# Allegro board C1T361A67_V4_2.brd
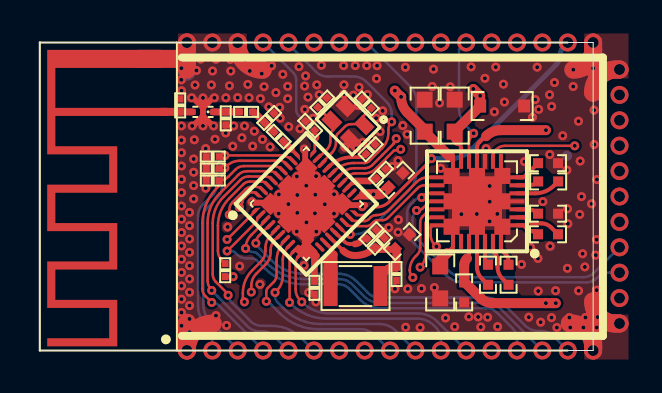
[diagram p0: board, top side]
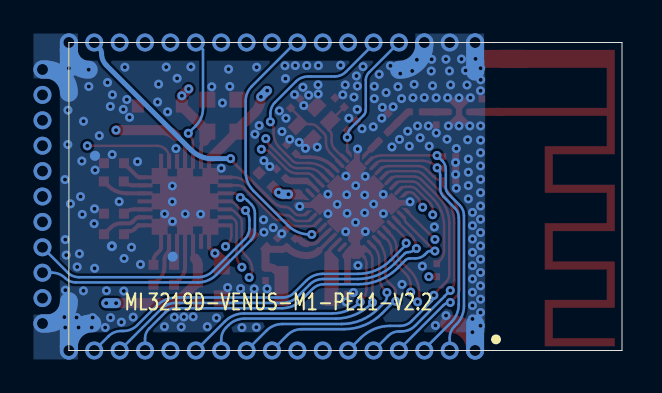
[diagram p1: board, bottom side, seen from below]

Outline 27.67 x 15.4 mm; copper layers: TOP, GND, POWER, BOTTOM. Coordinates in mm from the lower left corner of the outline.
Outline path: 0,15.4 27.67,15.4 27.67,0 26.4,0 0,0 0,15.4

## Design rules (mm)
constraint set DEFAULT: min track width 0.127, pair gap 0.1

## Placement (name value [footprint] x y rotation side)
C1  220pF  [0201]  11.94 10.69 135 top
C2  NC  [0201]  11.46 11.63 45 top
C3  NC  [0201]  9.29 11.61 270 top
C5  1uF  [0201]  13.51 11.24 315 top
C6  1uF  [0201]  16.54 10.06 45 top
C7  10uF  [0402]  17.8 8.52 45 top
C8  1uF  [0201]  17.06 8.84 45 top
C10  NC  [0201]  14.12 12.4 45 top
C11  NC  [0201]  16.35 12.35 315 top
C12  2.2uF  [0201]  13.73 3.14 90 top
C13  1uF  [0201]  16.58 5.82 45 top
C14  NC/2.2uF  [0201]  17.83 3.82 270 top
C15  1uF  [0402]  23.44 3.79 90 top
C16  1uF  [0402]  22.41 3.79 90 top
C17  47uF  [0603C]  20.02 3.4 270 top
C18  470nF  [0402]  25.41 5.81 180 top
C19  100nF  [0402]  25.41 6.84 180 top
C20  100nF  [0402]  21.22 2.91 90 top
C21  NC/3.9pF  [0201]  8.64 8.5 0 top
C22  NC/3.9pF  [0201]  8.64 9.1 0 top
C23  NC/3.9pF  [0201]  8.64 9.7 180 top
C24  10uF  [0402]  18.12 5.44 45 top
C25  0.1uF  [0201]  17 5.39 45 top
C26  100nF  [0402]  25.42 8.45 180 top
C27  100nF  [0402]  25.41 9.37 180 top
C28  47uF  [0603C]  19.24 11.74 90 top
C29  47uF  [0603C]  20.74 11.74 90 top
C30  LFB152G45CB2D320  [0402_D]  8.15 11.93 0 top
D1  ULC0322P10LV  [0201]  7.01 12.25 270 top
D2  PESD3V3L1BAF  [SOD323]  23.12 12.22 180 top
L1  0R  [0201]  10.31 11.93 180 top
L3  6.8uH  [1008L]  15.78 3.22 180 top
R1  510R  [0201]  9.27 4.02 90 top
U1  TL3219D  [QFN_4X4_38PIN_0P35_2P9X2P9]  13.32 7.33 45 top
U2  NEH7100  [QFN_4X4_28PIN_0P4_2P5X2P5]  21.86 7.46 180 top
U3  MODULE_15p4mm  [MODULE_BUTEO_EH_1211]  15.61 8.97 0 top
Y1  24MHz-12pF-+/-10ppm  [OSCCC160X200X065]  15.45 11.41 135 top

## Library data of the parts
C1-C3 C10 C11 = C1608_NC: User Part Number: pn; Tolerance: RichardLC
C5 C6 C8 C12-C14 C21-C23 C25 = C1005X5R1C104K: User Part Number: pn; Tolerance: RichardLC
C7 C15-C20 C24 C26-C29 = C1005X5R1C104K
C30 = C1608_NC_4
D1 = DIODE SCHOTTKY_0: User Part Number: pn; Tolerance: RichardLC
D2 = DIODE SCHOTTKY_0
L1 = MLK1608_000R: User Part Number: pn; Tolerance: RichardLC
L3 = IND_0: User Part Number: pn; Tolerance: RichardLC
R1 = RS0603K330JT: User Part Number: pn; Tolerance: RichardLC
U1 = TL3219D: Tolerance: RichardLC
U2 = TLSR9517C_9: Tolerance: RichardLC
U3 = TLSR8868ET48_14: User Part Number: PN
Y1 = CRYSTAL4/SM_0

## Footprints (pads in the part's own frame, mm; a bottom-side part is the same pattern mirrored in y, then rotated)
0201
  rect 0.35x0.33 smd: 1(-0.325,0) 2(0.325,0)
0402
  rect 0.5x0.5 smd: 1(-0.5,0) 2(0.5,0)
0402_D
  rect 0.3x0.3 smd: 1(0,0.3) 3(0,-0.3)
  rect 0.35x0.3 smd: 2(0.54,0) 4(-0.54,0)
0603C
  rect 0.8x0.8 smd: 1(-0.8,0) 2(0.8,0)
1008L
  rect 0.7x2 smd: 1(-1.25,0) 2(1.25,0)
MODULE_BUTEO_EH_1211
  rect 0.25x0.25 smd: 1(-8.255,-8.97) 2(-6.985,-8.97) 3(-5.715,-8.97) 4(-4.445,-8.97) 5(-3.175,-8.97) 6(-1.905,-8.97) 7(-0.635,-8.97) 8(0.635,-8.97) 9(1.905,-8.97) 10(3.175,-8.97) 11(4.445,-8.97) 12(5.715,-8.97) 13(6.985,-8.97) 14(8.255,-8.97) 15(9.525,-8.97) 16(10.795,-8.97) 17(12.065,-8.97) 18(13.385,-7.62) 19(13.385,-6.35) 20(13.385,-5.08) 21(13.385,-3.81) 22(13.385,-2.54) 23(13.385,-1.27) 24(13.385,0) 25(13.385,1.27) 26(13.385,2.54) 27(13.385,3.81) 28(13.385,5.08) 29(12.065,6.43) 30(10.795,6.43) 31(9.525,6.43) 32(8.255,6.43) 33(6.985,6.43) 34(5.715,6.43) 35(4.445,6.43) 36(3.175,6.43) 37(1.905,6.43) 38(0.635,6.43) 39(-0.635,6.43) 40(-1.905,6.43) 41(-3.175,6.43) 42(-4.445,6.43) 43(-5.715,6.43) 44(-6.985,6.43) 45(-8.255,6.43)
  rect 0.8x0.8 smd rot 45: 46(-2.281,0.155) 47(-3.179,-0.744) 48(-4.077,-1.641) 49(-1.383,-0.744) 50(-2.281,-1.641) 51(-3.179,-2.539) 52(-0.485,-1.641) 53(-1.383,-2.539)
  custom 0.2x0.2 smd rot 45: 54(-2.281,-4.003)
  rect 0.8x0.8 smd: 55(4.985,-0.241) 56(6.255,-0.241) 57(7.525,-0.241) 58(4.985,-1.512) 59(6.255,-1.512) 60(7.525,-1.512) 61(4.985,-2.781) 62(6.255,-2.781) 63(7.525,-2.781)
OSCCC160X200X065
  rect 0.85x0.6 smd: 1(-0.65,-0.45) 4(-0.65,0.55)
  rect 0.85x0.65 smd: 2(0.65,-0.45) 3(0.65,0.55)
QFN_4X4_28PIN_0P4_2P5X2P5
  rect 0.75x0.2 smd: 1(-2,1.2) 2(-2,0.8) 3(-2,0.4) 4(-2,0) 5(-2,-0.4) 6(-2,-0.8) 7(-2,-1.2) 15(2,-1.2) 16(2,-0.8) 17(2,-0.4) 18(2,0) 19(2,0.4) 20(2,0.8) 21(2,1.2)
  rect 0.2x0.75 smd: 8(-1.2,-2) 9(-0.8,-2) 10(-0.4,-2) 11(0,-2) 12(0.4,-2) 13(0.8,-2) 14(1.2,-2) 22(1.2,2) 23(0.8,2) 24(0.4,2) 25(0,2) 26(-0.4,2) 27(-0.8,2) 28(-1.2,2)
  rect 2.5x2.5 smd: 29(0,0)
QFN_4X4_38PIN_0P35_2P9X2P9
  custom 0.045x0.045 smd: 1(-2,1.575) 10(-2,-1.575) 11(-1.4,-2) 19(1.4,-2) 20(2,-1.575) 29(2,1.575) 30(1.4,2) 38(-1.4,2)
  oval 0.6x0.18 smd: 2(-2,1.225) 3(-2,0.875) 4(-2,0.525) 5(-2,0.175) 6(-2,-0.175) 7(-2,-0.525) 8(-2,-0.875) 9(-2,-1.225) 21(2,-1.225) 22(2,-0.875) 23(2,-0.525) 24(2,-0.175) 25(2,0.175) 26(2,0.525) 27(2,0.875) 28(2,1.225)
  oval 0.18x0.6 smd: 12(-1.05,-2) 13(-0.7,-2) 14(-0.35,-2) 15(0,-2) 16(0.35,-2) 17(0.7,-2) 18(1.05,-2) 31(1.05,2) 32(0.7,2) 33(0.35,2) 34(0,2) 35(-0.35,2) 36(-0.7,2) 37(-1.05,2)
  custom 0.725x0.725 smd: 39(0,0)
SOD323
  rect 0.6x0.65 smd: 1(-1.1,0) 2(1.1,0)

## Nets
GND: C2.2 C3.2 C5.1 C6.2 C7.2 C8.2 C10.2 C11.1 C12.1 C13.2 C14.2 C17.2 C19.1 C20.1 C21.1 C22.1 C23.2 C24.2 C25.2 C27.1 C28.2 C29.2 C30.1 C30.3 C30.4 D1.1 D1.2(CATHODE) D2.1 U1.39 U2.4 U2.10 U2.29 U3.1 U3.17 U3.18 U3.28 U3.29 U3.43 U3.44 U3.45 U3.46 U3.47 U3.48 U3.49 U3.50 U3.51 U3.52 U3.53 U3.54 U3.55 U3.56 U3.57 U3.58 U3.59 U3.60 U3.61 U3.62 U3.63 Y1.2 Y1.4
NEH_CSTORE: C17.1 U2.22 U3.25
NEH_HC0: U2.21 U3.24
NEH_HC1: U2.20 U3.23
NEH_HC2: U2.19 U3.22
NEH_HC3: U2.18 U3.21
NEH_HC4: U2.17 U3.20
NEH_LDOEN: U2.12 U3.34
NEH_SCL: U1.17 U2.16
NEH_SDA: U1.18 U2.15
NEH_USB: U2.11 U3.27
NEH_VBAT: C28.1 U2.14 U3.37
NEH_VBATOK: U2.9 U3.26
NEH_VIN: C20.2 U2.24 U3.19
NEH_VLDO: C29.1 D2.2(CATHODE) U2.13(VLDO) U3.35
TL_ANT: C1.1 U1.30
TL_AVDD1P25: C14.1 C24.1 C25.1 L3.1 U1.14
TL_AVDD3: C8.1 U1.22
TL_IR: U1.19 U3.30
TL_PA0: U1.37 U3.32
TL_PA1: U1.7 U3.9(PIN9)
TL_PA2: U1.8 U3.10
TL_PA3: U1.10 U3.12
TL_PA4: U1.9 U3.11
TL_PA5_DM: U1.6 U3.8
TL_PA6_DP: U1.5 U3.7
TL_PA7_SWS: R1.1 U3.13
TL_PB0: U1.1 U3.31
TL_PB1: U1.38 U3.33
TL_PB7: U1.16 U3.38
TL_PC0_AMICP: U1.23 U3.40
TL_PC1_AMICN: U1.24 U3.39
TL_PC2: U1.25 U3.41
TL_PD1: U1.2 U3.14
TL_PD4: U1.3 U3.15
TL_PD6: U1.4 U3.16
TL_PE2: C21.2 U1.33 U3.4
TL_PE4: C23.1 U1.31 U3.2
TL_PE5: C22.2 U1.32 U3.3
TL_PE6: U1.35 U3.6
TL_PE7: U1.34 U3.5
TL_RESET: C5.2 U1.29 U3.42
TL_VBAT: C7.1 U1.20 U3.36
TL_XC1: C10.1 U1.28 Y1.3
TL_XC2: C11.2 U1.27(XC2) Y1.1
N20494255: C1.2 C2.1 L1.1
N20494385: C3.1 C30.2 L1.2
N20502827: C6.1 U1.26
N20503268: C12.2 U1.11
N20503276: C13.1 U1.15
N20503917: L3.2 U1.13
N20508843: C16.1 U2.25
N20508848: C16.2 U2.26
N20508856: C15.1 U2.27
N20508888: C15.2 U2.28
N20508941: C18.2 U2.1
N20508944: C18.1 U2.2
N20508953: C26.1 U2.5
N20508962: C26.2 U2.6
N20508983: C19.2 U2.3
N20515790: C27.2 U2.7
N2050151623: R1.2 U1.36

Pads without a net: U1 12 21; U2 8 23

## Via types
v1: diameter 0.9, hole 0.55, TOP to BOTTOM, 45 vias
v2: diameter 0.45, hole 0.2, TOP to BOTTOM, 266 vias

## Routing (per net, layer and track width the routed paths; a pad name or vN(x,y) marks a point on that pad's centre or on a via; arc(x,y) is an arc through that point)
GND: length 74.4
  TOP w0.127: v2(16.12,7.2) 16.12,7.21 16.06,7.27
  TOP w0.2: 13.34,4.92 13.34,5.26 ; 13.34,5.26 13.19,5.41 ; 13.34,5.26 13.34,5.28 ; 13.26,9.3 13.15,9.19 ; 11.4,7.2 11.22,7.39 ; 13.33,7.34 U1.39 ; 13.26,9.45 13.45,9.26 ; 13.34,5.28 13.34,5.51 ; 13.34,5.28 13.61,5.54 ; 15.33,7.27 15.16,7.09 ; 15.44,7.27 15.19,7.52 ; 11.34,7.39 11.47,7.51
  TOP w0.29: 13.26,10.04 13.26,9.21 ; 16.27,7.27 16.24,7.27 16.17,7.2 16.13,7.2 16.13,7.2 v2(16.12,7.2) 16.11,7.21 16.11,7.21 16.05,7.27 15.07,7.27 ; 10.62,7.39 11.83,7.39
  TOP w0.3: 8.11,12.19 7.66,12.64 v2(7.59,12.64) ; v2(8.15,11.23) C30.3 C30.1 v2(8.15,12.63) ; 8.11,11.67 7.66,11.23 v2(7.61,11.23) ; v2(8.72,12.64) 8.65,12.64 8.2,12.19 ; 8.2,11.67 8.64,11.23 v2(8.69,11.23)
  TOP w0.35: 6.78,11.93 D1.2 C30.4
  TOP w0.4: 6.78,11.93 6.07,11.93
  TOP w0.9: 27.67,14.11 v2(27.67,14.11) 27.67,15.03 ; v1(9.89,15.4) 9.89,15.29 arc(10.26,14.41) 11.14,14.04 ; 7.35,0.05 7.35,1.39 ; 7.35,0.05 v1(7.35,0) ; 7.35,0.05 arc(7.73,0.97) 8.65,1.35 ; v1(7.35,15.4) 7.35,14.04 ; 4.88,14.58 v2(7.33,14.58) ; 27.67,1.46 27.67,0.19 ; 27.67,0.19 v1(27.67,0) ; 27.67,0.19 arc(27.33,1.01) 26.5,1.36 ; v1(27.67,15.4) 27.67,15.03 ; 27.67,15.03 arc(27.38,14.33) v2(26.68,14.04) ; v1(28.99,14.05) 28.82,14.05 arc(28,13.71) 27.66,12.89 ; v1(28.99,1.35) 28.78,1.35 arc(27.99,1.68) 27.67,2.46
  GND w0.9: v1(7.35,15.4) 7.35,13.93 ; v1(27.67,15.4) 27.67,15.03 arc(27.38,14.33) v2(26.68,14.04) ; v1(28.99,1.35) 28.78,1.35 arc(27.99,1.68) 27.67,2.46 ; 27.67,0.19 27.67,1.77 ; 27.67,0.19 v1(27.67,0) ; 27.67,0.19 arc(27.33,1.02) 26.5,1.36 ; 7.35,0.05 7.35,1.37 ; 7.35,0.05 v1(7.35,0) ; 7.35,0.05 arc(7.73,0.97) 8.65,1.35 ; v1(28.99,14.05) 28.83,14.05 arc(28,13.71) 27.66,12.88 ; v1(9.89,15.4) 9.89,15.29 arc(10.26,14.41) 11.14,14.04
  POWER w0.9: 27.67,15.03 v2(27.67,14.11) 27.67,14.03 ; 27.67,15.03 v1(27.67,15.4) ; 27.67,15.03 arc(27.38,14.33) v2(26.68,14.04) ; v1(27.67,0) 27.67,0.19 arc(27.33,1.02) 26.5,1.36 ; v1(7.35,15.4) 7.35,14.12 ; v1(9.89,15.4) 9.89,15.29 arc(10.26,14.4) 11.14,14.04 ; 7.35,0.05 7.35,1.47 ; 7.35,0.05 v1(7.35,0) ; 7.35,0.05 arc(7.73,0.97) 8.65,1.35
  BOTTOM w0.5: 26.36,9.74 arc(26.36,9.74) 26.37,9.73 ; v2(25.52,5.22) arc(25.52,5.21) 25.52,5.21 ; 22.48,4.69 arc(22.48,4.69) 22.47,4.69
  BOTTOM w0.9: v1(9.89,15.4) 9.89,15.29 arc(10.26,14.4) 11.15,14.03 ; v1(28.99,1.35) 28.78,1.35 arc(27.99,1.68) 27.67,2.46 ; v1(7.35,0) 7.35,1.34 ; 7.35,13.94 v1(7.35,15.4) ; v1(27.67,0) 27.67,0.19 ; 27.67,0.19 27.67,1.44 ; 27.67,0.19 arc(27.33,1.02) 26.5,1.36 ; v1(27.67,15.4) 27.67,15.03 ; 27.67,15.03 v2(27.67,14.11) ; 27.67,15.03 arc(27.38,14.33) v2(26.68,14.04) ; v1(28.99,14.05) 28.83,14.05 arc(28.01,13.71) 27.67,12.89
  vias: v1(8.62,15.4) v2(7.07,14.11) v2(7.07,13.53) v2(7.08,12.99) v2(7.07,11.23) v2(7.08,10.52) v2(7.08,9.89) v2(7.08,9.23) v2(7.08,8.56) v2(7.08,7.89) v2(7.08,7.23) v2(7.08,6.56) v2(7.08,5.9) v2(7.08,5.23) v2(7.08,4.56) v2(7.08,3.9) v2(7.08,3.23) v2(7.08,2.57) v2(7.08,1.9) v2(7.08,1.24) v2(7.48,6.9) v2(7.48,6.24) v2(7.48,5.57) v2(7.48,4.91) v2(7.48,4.24) v2(7.48,3.58) v2(7.48,2.91) v2(7.48,2.25) v2(7.48,1.58) v2(7.48,0.92) v2(7.69,9.57) v2(7.69,8.91) v2(7.69,8.25) v2(7.69,7.58) v2(7.76,13.27) v2(7.72,10.54) v2(7.83,14) v2(8.03,14.57) v2(8.29,10.1) v2(8.29,8.12) v2(8.33,9.4) v2(8.32,8.8) v2(8.58,13.28) v2(8.63,13.98) v2(8.75,10.56) v2(8.81,14.56) v2(8.8,1.75) v2(9.3,12.64) v2(9.29,10.88) v2(9.39,6.18) v2(9.33,1.25) v2(9.48,13.24) v2(9.52,14.56) v2(9.54,13.97) v2(9.69,11.23) v2(9.64,10.22) v2(9.89,12.64) v2(9.99,4.21) v2(10.1,10.64) v2(10.26,14.54) v2(10.23,11.23) v2(10.4,13.31) v2(10.5,13.98) v2(10.46,12.64) v2(10.64,10.22) v2(10.61,7.44) v2(10.72,10.96) v2(11.09,13.84) v2(11.03,12.6) v2(11,3.31) v2(11.13,10.55) v2(11.21,13.19) v2(11.45,12.18) v2(11.59,14.23) v2(11.51,10.18) v2(11.8,12.89) v2(11.99,12.16) v2(11.95,7.8) v2(11.94,6.85) v2(12.02,11.62) v2(12.15,13.81) v2(12.39,13.21) v2(12.39,12.59) v2(12.44,11.19) v2(12.43,7.32) v2(12.85,8.7) v2(12.87,7.77) v2(12.87,6.88) v2(12.84,5.95) v2(12.96,14.2) v2(13.01,11.09) v2(13.29,13.73) v2(13.24,13.22) v2(13.25,12.06) v2(13.23,10.07) v2(13.21,4.25) v2(13.32,8.24) v2(13.33,6.41) v2(13.41,12.67) v2(13.44,2.9) v2(13.66,11.61) v2(13.77,7.79) v2(13.75,6.86) v2(13.85,13.28) v2(13.81,8.72) v2(13.82,5.95) v2(13.8,2.43) v2(13.97,12.79) v2(14.08,14.26) v2(14.25,7.31) v2(14.71,7.81) v2(14.71,6.84) v2(15.19,14.25) v2(15.2,12.82) v2(15.21,13.29) v2(15.25,10.17) v2(15.67,12.77) v2(15.77,14.25) v2(15.84,10.11) v2(15.96,13.16) v2(15.92,12.25) v2(16.15,10.41) v2(16.35,14.25) v2(16.38,12.79) v2(16.62,10.56) v2(16.86,14.24) v2(16.84,13.59) v2(16.81,11.61) v2(17.01,10.95) v2(17.02,5.84) v2(17.14,11.98) v2(17.45,6.14) v2(17.62,9.2) v2(17.76,3.09) v2(17.91,9.49) v2(17.93,6.54) v2(17.91,5.91) v2(18.15,11.25) v2(18.28,14.16) v2(18.29,1.16) v2(18.36,10.81) v2(18.4,3.08) v2(19.08,3.1) v2(19.02,1.15) v2(19.68,14.07) v2(19.62,13.2) v2(19.73,3.15) v2(19.99,12.38) v2(20.05,9.11) v2(20.29,1.63) v2(20.52,13.19) v2(20.75,1.19) v2(21.08,6.82) v2(21.45,1.69) v2(21.57,14.18) v2(21.85,6.83) v2(21.92,1.68) v2(22.05,1.18) v2(22.26,13.61) v2(22.31,10.1) v2(22.39,1.66) v2(22.49,8.23) v2(22.5,7.44) v2(22.49,6.46) v2(22.73,11.93) v2(22.8,14.17) v2(22.88,6.83) v2(22.89,1.19) v2(23.18,13.32) v2(23.23,12.42) v2(24.09,4.31) v2(24.24,9.44) v2(24.45,1.67) v2(24.54,5.16) v2(24.64,11.66) v2(24.77,12.55) v2(24.87,14.17) v2(24.95,12.05) v2(24.91,4.6) v2(24.92,2.97) v2(25.04,1.42) v2(25.15,7.44) v2(25.49,12.79) v2(25.6,12.2) v2(25.5,9.8) v2(25.59,1.64) v2(25.74,13.4) v2(25.79,2.99) v2(25.86,1.15) v2(26.15,10.74) v2(26.36,9.02) v2(26.39,7.08) v2(26.38,4.11) v2(26.41,6.34) v2(26.48,1.65) v2(26.52,1.15) v2(26.67,13.2) v2(26.94,11.46) v2(26.94,2.98) v2(27.02,9.47) v2(27.09,7.7) v2(27,6.8) v2(27.14,4.84) v2(27.19,1.15) v2(27.26,4.18) v2(27.29,1.65) v2(27.59,7.33) v2(27.72,12.02) v2(27.72,10.3) v2(27.86,8.55) v2(27.85,5.55) v2(27.8,4.77) v2(27.85,3.02) v2(27.89,1.67) v2(27.85,1.15)
NEH_CSTORE: length 12.3
  TOP w0.2: v2(20.36,4.86) 20.66,5.16 U2.22
  TOP w0.5: C17.1 20.02,4.52 v2(20.36,4.86)
  POWER w0.4: v2(20.36,4.86) 22.72,4.86 arc(23.31,4.98) 23.82,5.32 28.74,10.24 v1(28.99,10.24)
NEH_HC0: length 14.1
  TOP w0.127: U2.21 19.66,6.26 19.54,6.14 19.54,5.76 arc(19.59,5.51) 19.73,5.3 v2(19.83,5.2)
  POWER w0.127: v1(28.99,8.97) 28.31,8.29 arc(28.12,8.01) 28.05,7.67 28.05,7.45 arc(28,7.16) 27.83,6.9 25.11,4.18 arc(24.72,3.93) 24.27,3.84 20.77,3.84 arc(20.34,3.92) 19.98,4.16 arc(19.94,4.21) 19.9,4.26 arc(19.85,4.34) 19.83,4.44 v2(19.83,5.2)
NEH_HC1: length 14.8
  TOP w0.127: U2.20 19.62,6.66 arc(19.51,6.64) 19.41,6.57 19.36,6.52 arc(19.31,6.44) 19.29,6.34 19.29,4.82 arc(19.22,4.46) v2(19.02,4.16)
  POWER w0.127: v1(28.99,7.7) 25.28,3.99 arc(24.82,3.69) 24.29,3.58 20.78,3.58 arc(20.32,3.66) 19.91,3.88 arc(19.79,3.95) 19.65,3.97 19.45,3.97 arc(19.23,4.02) 19.04,4.14 v2(19.02,4.16)
NEH_HC2: length 15.7
  TOP w0.127: U2.19 19.63,7.06 arc(19.51,7.03) 19.4,6.96 19.14,6.7 arc(19.05,6.57) 19.02,6.4 19.02,5.16 arc(18.98,4.95) 18.86,4.78 18.78,4.7 arc(18.57,4.39) 18.5,4.02 arc(18.54,3.82) v2(18.65,3.65)
  POWER w0.127: v2(18.65,3.65) 19.59,3.65 arc(19.79,3.61) 19.95,3.5 arc(20.24,3.37) 20.56,3.32 24.38,3.32 arc(24.93,3.43) 25.39,3.74 27.82,6.17 arc(28.11,6.36) 28.45,6.43 v1(28.99,6.43)
NEH_HC3: length 14.2
  TOP w0.127: U2.18 19.6,7.46 arc(19.5,7.44) 19.42,7.38 19.12,7.09 arc(19.03,7.02) 18.91,7 v2(18.84,7)
  BOTTOM w0.127: v1(28.99,5.16) 27.73,3.9 arc(27.47,3.73) 27.17,3.67 21.21,3.67 arc(20.81,3.74) 20.47,3.97 18.86,5.58 arc(18.69,5.83) 18.64,6.11 18.64,6.52 arc(18.69,6.78) v2(18.84,7)
NEH_HC4: length 14.8
  TOP w0.127: U2.17 19.42,7.86 arc(19.31,7.84) 19.22,7.77 v2(19.1,7.65)
  BOTTOM w0.127: v1(28.99,3.89) 28.51,3.89 arc(28.15,3.82) 27.85,3.62 arc(27.61,3.46) 27.34,3.4 21.21,3.4 arc(20.72,3.5) 20.3,3.78 18.57,5.51 arc(18.42,5.74) 18.36,6.01 18.36,6.87 arc(18.41,7.11) 18.55,7.31 18.75,7.51 arc(18.9,7.61) 19.09,7.65 v2(19.1,7.65)
NEH_LDOEN: length 6.4
  TOP w0.127: U2.12 21.46,10.3 arc(21.52,10.6) v2(21.69,10.86)
  BOTTOM w0.127: v1(21.32,15.4) 20.96,15.04 20.96,12.11 arc(21.05,11.63) 21.32,11.23 v2(21.69,10.86)
NEH_SCL: length 5.5
  TOP w0.127: U1.17 15.32,6.32 arc(15.44,6.24) 15.57,6.22 16.33,6.22 arc(16.47,6.24) 16.58,6.32 16.69,6.43 arc(16.79,6.49) 16.91,6.52 17.14,6.52 arc(17.28,6.55) 17.41,6.63 18.9,8.12 arc(19.05,8.22) 19.23,8.26 U2.16
NEH_SDA: length 5.2
  TOP w0.127: U1.18 15.59,6.55 arc(15.67,6.49) 15.77,6.47 16.23,6.47 arc(16.34,6.5) 16.44,6.56 16.53,6.65 arc(16.66,6.74) 16.82,6.77 arc(17.16,6.84) 17.45,7.03 18.84,8.42 arc(19.1,8.6) 19.41,8.66 U2.15
NEH_USB: length 8.9
  TOP w0.2: U2.11 21.86,10.13 arc(21.89,10.29) 21.98,10.42 22.26,10.7 22.3,10.7 22.32,10.72
  TOP w0.5: v2(25.31,11.02) 23.04,11.02 arc(22.65,10.94) 22.32,10.72
  POWER w0.5: v2(25.31,11.02) 26.74,12.45 arc(27.11,12.69) 27.54,12.78 v1(28.99,12.78)
NEH_VBAT: length 8.1
  TOP w0.2: 20.51,9.67 20.61,9.57 arc(20.65,9.52) U2.14
  TOP w0.5: 18.06,12.68 v2(18.06,12.68) ; v2(18.06,12.68) 18.06,12.67 18.06,12.67 17.75,12.98 v2(17.75,13) ; v2(18.06,12.68) 18.06,12.66 arc(18.15,12.25) 18.38,11.9 19.24,11.04 C28.1 20.51,9.67
  POWER w0.5: v2(18.06,12.68) v2(17.75,13) arc(17.57,13.26) 17.51,13.57 17.51,14.38 v1(17.51,15.4)
  BOTTOM w0.45: v2(17.75,13) v2(18.06,12.68)
NEH_VBATOK: length 7.4
  TOP w0.127: v2(26.75,10.23) 23.25,10.23 arc(23.02,10.19) 22.83,10.06 arc(22.7,9.87) 22.66,9.65 U2.9
  POWER w0.2: v1(28.99,11.51) 28.28,11.51 arc(28.04,11.46) 27.84,11.33 v2(26.75,10.23)
NEH_VIN: length 11.3
  TOP w0.2: U2.24 21.46,4.84 arc(21.43,4.71) 21.36,4.6
  TOP w0.5: v2(25.8,2.37) v2(25.31,2.37) 22.66,2.37 arc(22.32,2.43) 22.04,2.63 21.25,3.41 C20.2 21.22,4.26 arc(21.26,4.44) 21.36,4.6
  POWER w0.5: v2(25.31,2.37) v2(25.8,2.37) arc(25.81,2.37) 25.81,2.37 28.38,2.37 arc(28.71,2.43) v1(28.99,2.62)
  BOTTOM w0.5: v2(25.31,2.37) v2(25.8,2.37)
NEH_VLDO: length 7.8
  TOP w0.2: U2.13 21.06,10.08 arc(21.02,10.3) 20.89,10.48
  TOP w0.5: v2(21.68,13.08) v2(22.02,12.74) D2.2 20.74,10.95 C29.1 20.74,10.84 arc(20.78,10.65) 20.89,10.48
  POWER w0.5: v2(22.02,12.74) v2(21.68,13.08) 20.43,14.32 arc(20.15,14.75) 20.05,15.25 v1(20.05,15.4)
TL_ANT: length 1
  TOP w0.127: 12.87,9.76 U1.30
  TOP w0.18: 12.56,10.07 12.87,9.76
  TOP w0.35: C1.1 12.56,10.07
TL_AVDD1P25: length 6.1
  TOP w0.18: U1.14 15.15,5 arc(15.16,5) 15.16,5
  TOP w0.35: C24.1 17.74,5.06 17.02,5.06 arc(16.89,5.08) 16.78,5.16 C25.1 arc(16.32,4.86) 15.78,4.75 15.76,4.75 arc(15.43,4.82) 15.16,5
  TOP w0.4: L3.1 17.03,3.31 arc(17.11,3.7) 17.34,4.03 arc(17.46,4.12) 17.61,4.15 C14.1 17.83,4.93 arc(17.82,5.01) C24.1
TL_AVDD3: length 1.8
  TOP w0.18: 15.59,8.35 15.66,8.35 15.79,8.48 ; 15.59,8.35 15.72,8.49 ; 15.59,8.35 U1.22
  TOP w0.33: C8.1 16.82,8.61 arc(16.68,8.51) 16.51,8.48 15.79,8.48
TL_IR: length 14.4
  TOP w0.127: U1.19 15.78,6.85 arc(15.88,6.79) 15.99,6.77 16.16,6.77 arc(16.28,6.79) 16.37,6.86 16.58,7.06 arc(16.71,7.15) 16.86,7.18
  TOP w0.15: v2(19.58,9.59) 19.58,9.55 17.46,7.43 arc(17.18,7.24) 16.86,7.18
  BOTTOM w0.25: v1(26.4,15.4) 26.18,15.18 arc(26.07,15.02) 26.03,14.83 arc(25.97,14.53) 25.8,14.27 21.58,10.04 arc(21.16,9.75) 20.67,9.59 v2(19.58,9.59)
TL_PA0: length 24.7
  TOP w0.127: U1.37 11.11,8.06 arc(10.97,8.15) 10.8,8.19 10.58,8.19 arc(10.42,8.15) 10.28,8.06 9.63,7.41 arc(9.51,7.23) 9.47,7.02 v2(9.47,6.79)
  POWER w0.127: v1(23.86,15.4) 23.94,15.32 23.94,10.96 arc(23.89,10.69) 23.73,10.45 18.39,5.11 arc(18.1,4.92) 17.75,4.85 13.93,4.85 arc(13.04,5.02) 12.29,5.53 11.8,6.01 arc(11.44,6.25) 11.02,6.34 10.56,6.34 arc(9.97,6.46) v2(9.47,6.79)
TL_PA1: length 10.4
  TOP w0.127: v2(11.32,2.46) 11.32,2.95 arc(11.34,3.04) 11.39,3.12 11.69,3.42 arc(11.8,3.58) 11.83,3.76 11.83,4.46 arc(11.95,5.05) 12.28,5.54 U1.7
  BOTTOM w0.127: v1(17.51,0) 16.74,0.77 arc(16.41,0.99) 16.02,1.07 13.91,1.07 arc(12.87,1.27) 12,1.86 11.45,2.4 arc(11.39,2.44) v2(11.32,2.46)
TL_PA2: length 10.9
  TOP w0.127: v2(11.76,2.9) 11.84,2.98 arc(12.06,3.32) 12.14,3.72 12.14,4.52 arc(12.22,4.88) 12.42,5.19 U1.8
  BOTTOM w0.127: v1(18.78,0) 17.78,1 arc(17.42,1.24) 16.99,1.32 14.03,1.32 arc(13.04,1.52) 12.21,2.08 11.91,2.38 arc(11.79,2.55) 11.75,2.76 11.75,2.88 ; 11.75,2.88 11.75,2.89 ; 11.75,2.88 arc(11.75,2.89) v2(11.76,2.9)
TL_PA3: length 11.9
  TOP w0.127: 12.86,4.64 U1.10 12.94,4.71 arc(12.83,4.55) 12.79,4.35 12.79,3.05 arc(12.85,2.76) 13.01,2.51 v2(13.1,2.43) 13.07,2.46
  BOTTOM w0.127: v1(21.32,0) 19.87,1.45 arc(19.42,1.75) 18.9,1.85 14.49,1.85 arc(13.73,2) v2(13.1,2.43)
TL_PA4: length 11.6
  TOP w0.127: v2(12.48,2.4) 12.48,4.54 arc(12.52,4.74) 12.64,4.91 U1.9
  BOTTOM w0.127: v1(20.05,0) 20.05,0.55 arc(19.99,0.87) 19.8,1.15 19.69,1.26 arc(19.32,1.51) 18.88,1.6 14.32,1.6 arc(13.37,1.78) 12.57,2.32 v2(12.48,2.4)
TL_PA5_DM: length 10.5
  TOP w0.127: v2(10.57,2.92) 10.57,3.23 arc(10.64,3.56) 10.82,3.84 11.29,4.31 arc(11.47,4.58) 11.54,4.91 11.54,5.02 arc(11.6,5.31) 11.76,5.56 12,5.79 U1.6
  POWER w0.127: v1(16.24,0) 15.49,0.75 arc(14.55,1.38) 13.45,1.6 11.46,1.6 arc(11.12,1.66) 10.83,1.85 arc(10.71,2.03) 10.67,2.24 10.67,2.67 arc(10.65,2.81) v2(10.57,2.92)
TL_PA6_DP: length 10.3
  TOP w0.127: U1.5 11.79,6 11.54,5.75 arc(11.35,5.47) 11.28,5.13 11.28,4.99 arc(11.22,4.7) 11.06,4.45 10.62,4.01 arc(10.27,3.49) 10.15,2.88 10.15,2.62 arc(10.17,2.52) v2(10.23,2.43)
  POWER w0.127: v1(14.97,0) 14.97,0.52 arc(14.94,0.66) 14.86,0.78 arc(14.25,1.19) 13.53,1.33 11.49,1.33 arc(10.97,1.44) 10.53,1.73 10.5,1.76 arc(10.3,2.07) v2(10.23,2.43)
TL_PA7_SWS: length 14.7
  TOP w0.127: R1.1 v2(9.66,3.69)
  POWER w0.127: v1(22.59,0) 22.53,0 20.7,1.83 arc(20.4,2.03) 20.05,2.1 15.45,2.1 arc(14.97,2.2) 14.56,2.47 13.87,3.16 arc(13.23,3.59) 12.48,3.74 9.78,3.74 arc(9.72,3.73) v2(9.66,3.69)
TL_PB0: length 25.2
  TOP w0.127: v2(9.36,5.55) 10.8,6.99 U1.1
  POWER w0.127: v1(25.13,15.4) 25.13,15.34 24.39,14.6 arc(24.25,14.39) 24.2,14.14 24.2,10.88 arc(24.14,10.59) 23.98,10.34 18.53,4.89 arc(18.19,4.66) 17.78,4.58 13.94,4.58 arc(12.95,4.78) 12.12,5.33 11.64,5.81 arc(11.35,6.01) 11,6.08 10.2,6.08 arc(9.91,6.02) 9.66,5.86 v2(9.36,5.55)
TL_PB1: length 23.1
  TOP w0.127: U1.38 10.82,7.85 arc(10.75,7.9) 10.67,7.91 10.61,7.91 arc(10.51,7.89) 10.42,7.83 10.4,7.82 10.29,7.7 10.21,7.63 arc(10.15,7.53) 10.12,7.41 arc(10.07,7.28) 9.98,7.17 v2(9.97,7.16)
  POWER w0.127: v1(22.59,15.4) 23.48,14.51 arc(23.63,14.29) 23.68,14.03 23.68,11.05 arc(23.63,10.78) 23.48,10.56 18.27,5.34 arc(18,5.16) 17.68,5.1 14.06,5.1 arc(13.16,5.28) 12.4,5.79 12,6.18 arc(11.55,6.49) 11.01,6.59 arc(10.58,6.68) 10.21,6.93 v2(9.97,7.16)
TL_PB7: length 13
  TOP w0.127: U1.16 15.22,5.93 arc(15.36,5.83) v2(15.52,5.8)
  BOTTOM w0.127: v2(15.52,5.8) 15.63,5.8 arc(16.21,5.92) 16.7,6.25 18.43,7.97 arc(18.72,8.41) 18.83,8.94 18.83,12.47 arc(18.75,12.87) 18.52,13.21 16.33,15.4 v1(16.24,15.4)
TL_PC0_AMICP: length 13.2
  TOP w0.127: U1.23 15.48,8.74 arc(15.6,8.82) 15.75,8.85 16.23,8.85 arc(16.54,8.92) 16.8,9.09 16.84,9.13 17.39,9.67 17.7,9.99 17.99,10.05 18.03,10.05 v2(18.04,10.06)
  POWER w0.127: v1(13.7,15.4) 14.29,14.81 arc(14.44,14.58) 14.5,14.31 14.5,10.22 arc(14.55,9.94) 14.71,9.7 14.75,9.66 arc(15.06,9.46) 15.41,9.38 16.64,9.38 arc(17.05,9.47) 17.39,9.7 17.56,9.86 arc(17.78,10.01) v2(18.04,10.06)
TL_PC1_AMICN: length 12.8
  TOP w0.127: v2(17.82,10.59) 17.82,10.59 17.82,10.49 17.68,10.35 17.68,10.33 17.13,9.78 16.62,9.27 arc(16.45,9.16) 16.25,9.12 ; 15.1,8.86 arc(15.39,9.05) 15.72,9.12
  TOP w0.128: U1.24 15.1,8.86 ; 15.72,9.12 16.25,9.12
  POWER w0.127: v1(14.97,15.4) 14.76,15.19 14.76,10.27 arc(14.8,10.04) 14.92,9.86 14.93,9.85 arc(15.16,9.7) 15.43,9.65 16.62,9.65 arc(16.95,9.71) 17.23,9.9 17.28,9.95 17.74,10.41 arc(17.8,10.5) v2(17.82,10.59)
TL_PC2: length 11.6
  TOP w0.127: 16.88,9.88 17.12,10.12 arc(17.35,10.47) 17.43,10.88 17.43,11.04 arc(17.47,11.25) v2(17.59,11.44) ; U1.25 14.72,8.97 arc(15.17,9.27) 15.69,9.37 ; 16.23,9.37 arc(16.36,9.4) 16.46,9.47
  TOP w0.128: 16.46,9.47 16.88,9.88 ; 15.69,9.37 16.23,9.37
  BOTTOM w0.127: v2(17.59,11.44) 17.59,11.85 arc(17.53,12.15) 17.36,12.4 16.32,13.44 arc(16.03,13.63) 15.69,13.7 15.54,13.7 14.54,13.7 14.37,13.7 arc(14.07,13.76) 13.81,13.94 12.43,15.31 v1(12.43,15.4)
TL_PD1: length 19.3
  TOP w0.127: v2(9.36,4.97) 9.37,4.97 10.79,6.39 arc(10.86,6.5) 10.88,6.62 U1.2
  BOTTOM w0.127: v2(9.36,4.97) 9.59,4.97 arc(9.68,4.96) 9.75,4.91 9.86,4.8 arc(10.07,4.66) 10.33,4.61 10.61,4.61 arc(10.73,4.58) 10.84,4.51 11.23,4.12 arc(11.36,4) 11.5,3.89 arc(12.29,3.46) 13.18,3.31 14.92,3.31 arc(15.22,3.26) 15.47,3.09 16.04,2.52 arc(16.49,2.22) 17.01,2.11 22.35,2.11 arc(22.62,2.06) 22.84,1.91 23.65,1.1 23.66,1.09 arc(23.81,0.87) 23.86,0.61 v1(23.86,0)
TL_PD4: length 18.5
  TOP w0.127: U1.3 11.29,6.5 10.58,5.79 10.56,5.77 arc(10.36,5.46) v2(10.29,5.1)
  BOTTOM w0.127: v1(25.13,0) 23.04,2.09 arc(22.72,2.3) 22.33,2.38 17,2.38 arc(16.58,2.46) 16.22,2.7 15.63,3.29 arc(15.32,3.5) 14.95,3.57 13.21,3.57 arc(12.23,3.77) 11.39,4.33 10.87,4.85 arc(10.8,4.9) 10.71,4.92 arc(10.49,4.96) 10.3,5.09 v2(10.29,5.1)
TL_PD6: length 18.8
  TOP w0.127: U1.4 11.5,6.29 11.03,5.81 10.95,5.74 arc(10.84,5.57) v2(10.8,5.37)
  BOTTOM w0.127: v1(26.4,0) 25.69,0.71 arc(25.4,0.91) 25.05,0.98 24.95,0.98 arc(24.57,1.05) 24.25,1.27 23.28,2.24 arc(22.82,2.54) 22.28,2.65 16.97,2.65 arc(16.66,2.71) 16.4,2.89 15.79,3.5 arc(15.42,3.74) 14.98,3.83 13.2,3.83 arc(12.33,4.01) 11.58,4.5 10.85,5.23 arc(10.81,5.29) v2(10.8,5.37)
TL_PE2: length 13.6
  TOP w0.127: U1.33 12.09,9.06 arc(11.91,9.18) 11.69,9.22 10.19,9.22 arc(9.97,9.18) 9.79,9.06 9.42,8.68 arc(9.21,8.55) C21.2 8.97,8.3 arc(8.96,8.25) 8.93,8.21 8.86,8.14 arc(8.32,7.33) 8.13,6.36 8.13,3.07 arc(8.16,2.88) 8.27,2.72 v2(8.59,2.4)
  BOTTOM w0.127: v1(11.16,0) 11.16,0.04 8.94,2.26 arc(8.78,2.36) v2(8.59,2.4)
TL_PE4: length 14.2
  TOP w0.127: C23.1 9.13,9.7 arc(9.2,9.71) v2(9.25,9.75) 9.26,9.75 12,9.75 arc(12.35,9.68) U1.31
  BOTTOM w0.127: v2(9.25,9.75) 8.99,9.48 arc(8.86,9.29) 8.82,9.07 8.82,8.15 arc(8.78,7.97) 8.68,7.82 8.12,7.26 arc(7.96,7.03) 7.91,6.75 7.91,2.22 arc(8.01,1.73) 8.29,1.31 8.38,1.21 arc(8.56,0.95) 8.62,0.63 v1(8.62,0)
TL_PE5: length 13.8
  TOP w0.127: C22.2 9.16,9.1 arc(9.21,9.11) v2(9.25,9.14) 9.32,9.21 arc(9.63,9.41) 9.99,9.49 12.01,9.49 arc(12.15,9.46) 12.26,9.38 12.41,9.24
  BOTTOM w0.127: v1(9.89,0) 9.89,0.07 8.54,1.42 arc(8.26,1.83) 8.17,2.31 8.17,6.65 arc(8.22,6.91) 8.36,7.12 8.92,7.69 arc(9.05,7.87) 9.1,8.1 9.1,8.77 arc(9.13,8.97) v2(9.25,9.14)
TL_PE6: length 13.7
  TOP w0.127: U1.35 11.58,8.58 arc(11.44,8.67) 11.28,8.7 10.43,8.7 arc(10.22,8.66) 10.03,8.54 9.19,7.69 arc(8.78,7.08) 8.64,6.36 8.64,3.81 arc(8.68,3.6) 8.8,3.43 9.37,2.85 arc(9.4,2.81) v2(9.41,2.76)
  BOTTOM w0.127: v1(13.7,0) 13.08,0.62 arc(12.4,1.07) 11.61,1.23 11.11,1.23 arc(10.79,1.29) 10.52,1.47 9.54,2.46 arc(9.44,2.6) v2(9.41,2.76)
TL_PE7: length 13.5
  TOP w0.127: U1.34 11.8,8.85 arc(11.68,8.93) 11.53,8.96 10.35,8.96 arc(10.12,8.92) 9.93,8.79 8.99,7.85 arc(8.54,7.18) 8.38,6.39 8.38,3.5 arc(8.44,3.23) v2(8.59,3)
  BOTTOM w0.127: v1(12.43,0) 11.71,0.72 arc(11.45,0.89) 11.15,0.95 11.03,0.95 arc(10.66,1.03) 10.35,1.24 8.88,2.71 8.88,2.71 v2(8.59,3)
TL_RESET: length 6.9
  TOP w0.127: U1.29 13.74,9.98 v2(13.74,10.66) C5.2
  BOTTOM w0.127: v1(11.16,15.4) 12.66,13.9 arc(12.78,13.72) 12.82,13.52 12.82,12.03 arc(12.85,11.88) 12.93,11.75 13.57,11.12 arc(13.7,10.92) 13.74,10.7 v2(13.74,10.66)
TL_VBAT: length 12.7
  TOP w0.127: v2(17.18,7.9) 17.08,7.81 16.95,7.81 17.31,8.17 C7.1 ; v2(16.68,7.81) 16.63,7.81 16.45,7.63 ; 16.2,7.81 16.02,7.63
  TOP w0.14: 16.45,7.63 U1.20
  TOP w0.5: v2(16.68,7.81) 16.95,7.81 arc(17.07,7.83) v2(17.18,7.9) C7.1 ; 16.63,7.81 16.2,7.81
  POWER w0.5: v2(16.68,7.81) 16.95,7.81 arc(17.07,7.83) v2(17.18,7.9) 18.64,9.36 arc(18.89,9.74) 18.98,10.19 18.98,14.92 arc(18.93,15.18) v1(18.78,15.4)
  BOTTOM w0.45: v2(16.68,7.81) 16.95,7.81 arc(17.07,7.83) v2(17.18,7.9)
TL_XC1: length 3.2
  TOP w0.127: C10.1 14.45,11.61 14.47,11.61 Y1.3 14.68,11.4 14.68,11.05 14.62,10.98 arc(14.55,10.88) 14.53,10.77 14.53,10.47 arc(14.48,10.25) 14.36,10.06 13.91,9.61 U1.28
TL_XC2: length 4.3
  TOP w0.127: U1.27 14.12,9.4 14.57,9.85 arc(14.75,10.11) 14.81,10.42 14.81,10.63 arc(14.83,10.74) 14.89,10.83 15.24,11.19 arc(15.39,11.28) 15.56,11.32 16.17,11.32 ; 16.17,11.32 Y1.1 ; 16.17,11.32 16.13,11.36 16.13,11.68 C11.2
N20494255: length 1.5
  TOP w0.35: C1.2 C2.1 10.75,11.88 arc(10.7,11.92) L1.1
N20494385: length 1.3
  TOP w0.35: L1.2 C3.1 C30.2
N20502827: length 2.2
  TOP w0.18: U1.26 14.44,9.19 arc(14.97,9.54) 15.59,9.66 16.05,9.67 arc(16.14,9.68) 16.21,9.73 C6.1
N20503268: length 2.1
  TOP w0.18: U1.11 13.75,4.53 arc(13.74,4.51) 13.73,4.49
  TOP w0.33: 13.73,4.49 13.73,4.84 ; 13.73,4.49 C12.2 ; 13.73,4.49 arc(13.76,4.62) 13.83,4.73
N20503276: length 1.9
  TOP w0.18: U1.15 14.76,5.91 15.23,5.44 arc(15.36,5.36) 15.52,5.33 15.75,5.33
  TOP w0.33: C13.1 16.17,5.59 16.01,5.43 arc(15.89,5.35) 15.75,5.33
N20503917: length 4.2
  TOP w0.18: U1.13 14.55,5.11 arc(14.65,4.97) 14.68,4.8
  TOP w0.4: 14.68,4.8 14.38,4.5 14.38,3.37 L3.2 14.68,3.37 14.68,4.8
N20508843: length 2.4
  TOP w0.2: U2.25 21.86,4.18 arc(21.92,3.86) 22.1,3.6 C16.1
N20508848: length 1.2
  TOP w0.2: C16.2 22.26,4.44 U2.26
N20508856: length 2.4
  TOP w0.2: U2.27 22.66,5.1 arc(22.69,4.96) 22.77,4.84 arc(22.86,4.7) 22.89,4.54 22.89,4.16 arc(22.95,3.86) 23.12,3.61 C15.1
N20508888: length 1.3
  TOP w0.2: U2.28 23.06,5.14 arc(23.07,5.06) 23.12,5 23.29,4.82 arc(23.4,4.66) 23.44,4.47 C15.2
N20508941: length 1.2
  TOP w0.2: U2.1 24.2,6.26 24.39,6.07 arc(24.5,5.99) 24.64,5.96 24.76,5.96 C18.2
N20508944: length 2.4
  TOP w0.2: C18.1 25.57,6.15 arc(25.34,6.31) 25.07,6.36 24.64,6.36 arc(24.57,6.37) 24.5,6.42 24.33,6.59 arc(24.25,6.64) 24.16,6.66 U2.2
N20508953: length 2.3
  TOP w0.2: U2.5 24.77,7.86 arc(25.28,7.96) 25.72,8.25 C26.1
N20508962: length 1.1
  TOP w0.2: U2.6 24.45,8.26 arc(24.7,8.31) 24.92,8.45 C26.2
N20508983: length 1.1
  TOP w0.2: U2.3 24.39,7.06 arc(24.67,7) C19.2
N20515790: length 1.3
  TOP w0.2: U2.7 24.12,8.66 arc(24.2,8.67) 24.26,8.72 C27.2
N2050151623: length 5.9
  TOP w0.127: 11.42,8.25 11.3,8.37 arc(11.21,8.43) 11.1,8.45 10.5,8.45 arc(10.32,8.41) 10.17,8.31 9.46,7.6 arc(9.05,6.98) 8.9,6.24 8.9,4.98 arc(8.95,4.73) 9.09,4.51 R1.2

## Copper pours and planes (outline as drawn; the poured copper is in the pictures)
GND on TOP (solid shape): 6.08,14.13 0.77,14.13 0.77,12.13 6.37,12.13 6.37,11.73 0.77,11.73 0.77,10.21 3.87,10.21 3.87,7.89 0.77,7.89 0.77,6.37 3.87,6.37 3.87,4.05 0.77,4.05 0.77,2.53 3.87,2.53 3.87,0.21 0.37,0.21 0.37,0.61 3.47,0.61 3.47,2.13 0.37,2.13 0.37,4.45 3.47,4.45 3.47,5.97 0.37,5.97 0.37,8.29 3.47,8.29 3.47,9.81 0.37,9.81 0.37,15.03 6.08,15.03
GND on TOP: 6.85,14.49 28.12,14.49 28.12,0.91 6.85,0.91 6.85,11.45 10.56,11.45 11.96,10.05 11.96,9.92 12.13,9.92 12.25,10.04 10.69,11.6 10.38,11.6 10.35,11.57 10.35,11.73 7.97,11.73 8.04,11.8 8.04,12.08 7.99,12.13 10.35,12.13 10.35,12.23 12.8,9.77 13,9.77 13,10.31 10.9,12.41 6.85,12.41 ; 19 cut-outs
GND on TOP, BOTTOM, GND, POWER: 10.34,14.09 10.34,15.85 6.9,15.85 6.9,14.09
GND on TOP, BOTTOM, GND, POWER: 27.22,15.85 27.22,13.6 29.44,13.6 29.44,15.85
GND on TOP, BOTTOM, GND, POWER: 29.44,1.8 29.44,-0.45 27.22,-0.45 27.22,1.8
GND on BOTTOM: 28.12,0.91 28.12,14.49 6.85,14.49 6.85,0.91 ; 2 cut-outs
GND on GND, POWER: 28.12,0.91 28.12,14.49 6.85,14.49 6.85,0.91

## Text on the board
Ref Des/Silkscreen Bottom: ML3219D-VENUS-M1-PE11-V2.2
User.Comments: #4 | #3 | #1 | #2 | TOP | #5
User.6: FIGURE | FINISHED_SIZE | 0.2 | 0.55 | DRILL CHART: TOP to BOTTOM | ALL UNITS ARE IN MILLIMETERS | PLATED | QTY | 266 | 45
